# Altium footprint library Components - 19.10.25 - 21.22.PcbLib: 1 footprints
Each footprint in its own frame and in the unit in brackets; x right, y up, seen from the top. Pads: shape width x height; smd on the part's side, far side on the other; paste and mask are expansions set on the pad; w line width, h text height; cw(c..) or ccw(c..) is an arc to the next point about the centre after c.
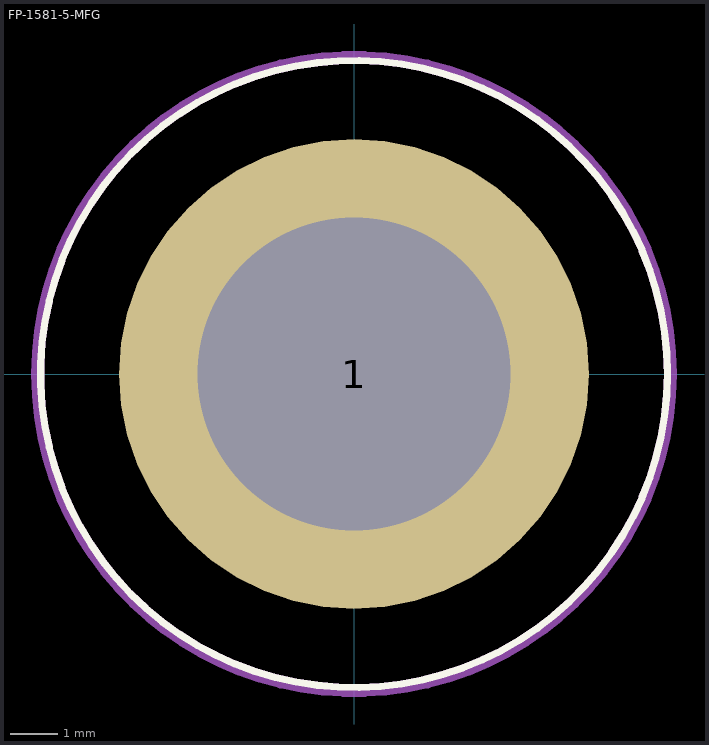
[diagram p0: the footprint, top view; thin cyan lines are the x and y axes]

## FP-1581-5-MFG [mm]
pads (1):
  round 9.9 hole 6.6 paste-2539.97 mask+0: 1(0,0)
Top Overlay:
  circle w0.15: c0,0 r6.604
Top Assembly:
  text ".Designator" at 0,0.188 h1
Top 3D Body:
  circle w0.15: c0,0 r6.604
Top Courtyard:
  lines w0.2: -6.704,0 ccw(c0,0) 6.704,0 ccw(c0,0) -6.704,0
Top Component Center:
  lines w0.1: -0.5,0 0.5,0 ; 0,-0.5 0,0.5
3D body "Conn_Pomona_Electronics_1581-5_eec.STEP": height 0.25, standoff 0, extent -6.704,-6.704 6.704,6.704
